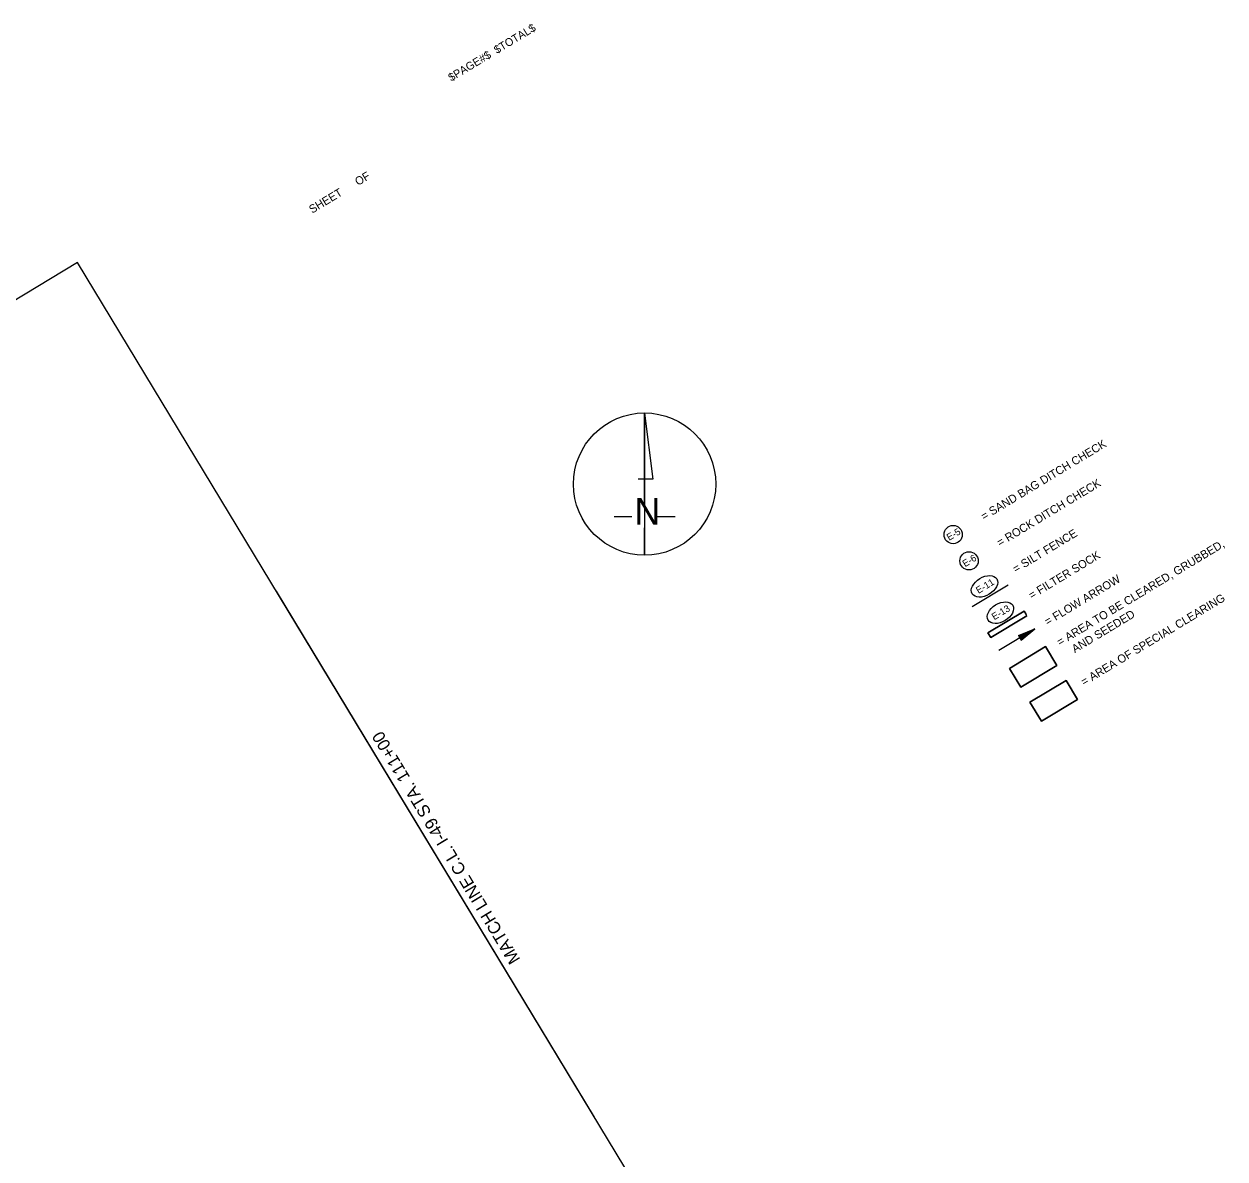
# Model space of a CAD drawing. Extents: x 627457 to 631191, y 366622 to 369946.
# Drawn here: x 629432 to 631191, y 368284 to 369946 of the extents above; entities that cross this region are included whole.
import ezdxf

# ---------------------------------------------------------------- set-up
doc = ezdxf.new("R2010")
doc.units = 0
for name, color, linetype in [('Copy of R_Dimension', 7, 'Continuous'), ('GN_Dimension', 7, 'Continuous'), ('R_Draft', 7, 'Continuous'), ('R_Horz Alg Side', 7, 'Continuous'), ('S_DITCHLINE', 7, 'Continuous'), ('S_ELECTRIC_UTILITIES', 7, 'Continuous')]:
    doc.layers.add(name, color=color, linetype=linetype)

# ---------------------------------------------------------------- blocks, each defined once
blk = doc.blocks.new('SHT-INFO-CELL_2 TITLE LINES')
at = {"layer": 'Copy of R_Dimension'}
for s, p in [('SHEET', (14.4405, 10.0545)), ('OF', (14.8333, 10.0545))]:
    blk.add_text(s, height=0.06, dxfattribs=at).set_placement(p)

msp = doc.modelspace()

# ---------------------------------------------------------------- linework, layer by layer
at = {"layer": 'Copy of R_Dimension'}
msp.add_line((630340.7, 369376.8), (630340.7, 369168.5), dxfattribs=at)
msp.add_lwpolyline([(630558.2, 367864.4), (629510.2, 369597.3), (629510.2, 369597.3), (627456.6, 368355.4), (628504.6, 366622.4)], close=True, dxfattribs=at)
msp.add_circle((630340.7, 369272.7), 104.2, dxfattribs=at)
at = {"layer": 'GN_Dimension'}
for p, q in [((630340.7, 369376.8), (630352.9, 369279.9)), ((630340.7, 369241.2), (630340.7, 369376.8)), ((630331.3, 369280.6), (630352.9, 369280.6)), ((630296.1, 369225.3), (630321.9, 369225.3)), ((630357.8, 369225.3), (630385.3, 369225.3)), ((630340.7, 369168.5), (630340.7, 369208.4))]:
    msp.add_line(p, q, dxfattribs=at)
at = {"layer": 'R_Draft'}
msp.add_line((630267.1, 368345.8), (629801.4, 369115.9), dxfattribs=at)
at = {"layer": 'R_Horz Alg Side'}
for p, q in [((630896.5, 369086.8), (630843.6, 369054.8)), ((630900.5, 369080), (630847.7, 369048)), ((630847.7, 369048), (630900.5, 369080)), ((630896.5, 369086.8), (630899.5, 369081.7)), ((630900.5, 369080), (630896.5, 369086.8)), ((630847.7, 369048), (630843.6, 369054.8)), ((630843.6, 369054.8), (630847.7, 369048)), ((630912.2, 369060.8), (630859.3, 369028.8)), ((630888.4, 369050.9), (630912.2, 369060.8)), ((630888.7, 369050.3), (630908.5, 369058.6)), ((630889, 369049.8), (630904.8, 369056.3)), ((630889.4, 369049.2), (630901.1, 369054.1)), ((630891.3, 369046), (630901.1, 369054.1)), ((630891.7, 369045.4), (630904.8, 369056.3)), ((630892, 369044.9), (630908.5, 369058.6)), ((630892.3, 369044.3), (630912.2, 369060.8)), ((630888.4, 369050.9), (630892.3, 369044.3)), ((630889.7, 369048.7), (630897.4, 369051.9)), ((630890, 369048.1), (630893.8, 369049.7)), ((630890.6, 369047.1), (630893.8, 369049.7)), ((630891, 369046.5), (630897.4, 369051.9)), ((630875, 369002.8), (630927.9, 369034.8)), ((630927.9, 369034.8), (630875, 369002.8)), ((630927.9, 369034.8), (630944.6, 369007.2)), ((630944.6, 369007.2), (630927.9, 369034.8)), ((630891.7, 368975.2), (630875, 369002.8)), ((630875, 369002.8), (630891.7, 368975.2)), ((630944.6, 369007.2), (630891.7, 368975.2)), ((630891.7, 368975.2), (630944.6, 369007.2)), ((630905, 368953.2), (630957.9, 368985.1)), ((630957.9, 368985.1), (630974.6, 368957.5)), ((630921.8, 368925.5), (630905, 368953.2)), ((630974.6, 368957.5), (630921.8, 368925.5))]:
    msp.add_line(p, q, dxfattribs=at)
msp.add_lwpolyline([(630843.6, 369054.8), (630896.5, 369086.8)], dxfattribs=at)
for centre in [(630792.6, 369198.8), (630815.9, 369160.3)]:
    msp.add_circle(centre, 13.4, dxfattribs=at)
for centre in [(630838.5, 369122.9), (630861.8, 369084.3)]:
    msp.add_ellipse(centre, major_axis=(18, 10.9), ratio=0.638788, dxfattribs=at)
at = {"layer": 'S_DITCHLINE'}
msp.add_lwpolyline([(630820.3, 369093.3), (630873.2, 369125.3)], dxfattribs=at)
at = {"layer": 'S_ELECTRIC_UTILITIES'}
for p, q in [((630957.9, 368985.1), (630905, 368953.2)), ((630974.6, 368957.5), (630957.9, 368985.1)), ((630905, 368953.2), (630921.8, 368925.5)), ((630921.8, 368925.5), (630974.6, 368957.5))]:
    msp.add_line(p, q, dxfattribs=at)

# ---------------------------------------------------------------- block references
at = {"layer": 'Copy of R_Dimension', "xscale": 200.00000000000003, "yscale": 199.99999999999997, "rotation": 31.163843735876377}
msp.add_blockref('SHT-INFO-CELL_2 TITLE LINES', (628423, 366453.3), dxfattribs=at)

# ---------------------------------------------------------------- texts
at = {"layer": 'GN_Dimension'}
msp.add_text('N', height=38.8, rotation=360, dxfattribs=at).set_placement((630326, 369213.3))
at = {"layer": 'R_Draft'}
for s, p in [('$TOTAL$', (630124.4, 369902.4)), ('$PAGE#$', (630057.5, 369861.9))]:
    msp.add_text(s, height=11.72, rotation=31.1638, dxfattribs=at).set_placement(p)
at = {"layer": 'R_Horz Alg Side'}
for s, p in [('E-5', (630786.8, 369189.5)), ('E-6', (630810, 369150.9)), ('E-11', (630829.7, 369111.8)), ('E-13', (630852.8, 369073.2))]:
    msp.add_text(s, height=10, rotation=31.1638, dxfattribs=at).set_placement(p)
at = {"layer": 'S_DITCHLINE'}
msp.add_text('MATCH LINE C.L. I-49 STA. 111+00', height=18, rotation=121.1638, dxfattribs=at).set_placement((630159.1, 368576.6))
at = {"layer": 'S_ELECTRIC_UTILITIES'}
for s, p in [('= SAND BAG DITCH CHECK', (630837.8, 369219.2)), ('= ROCK DITCH CHECK', (630861.1, 369180.7)), ('= SILT FENCE', (630884.4, 369142.2)), ('= AREA TO BE CLEARED, GRUBBED,', (630949, 369035.2)), ('= FILTER SOCK', (630907.6, 369103.6)), ('= FLOW ARROW', (630930.9, 369065.1)), ('= AREA OF SPECIAL CLEARING', (630984.3, 368976.9)), ('   AND SEEDED', (630959.4, 369018.1))]:
    msp.add_text(s, height=12, rotation=31.1638, dxfattribs=at).set_placement(p)

doc.saveas('drawing.dxf')
